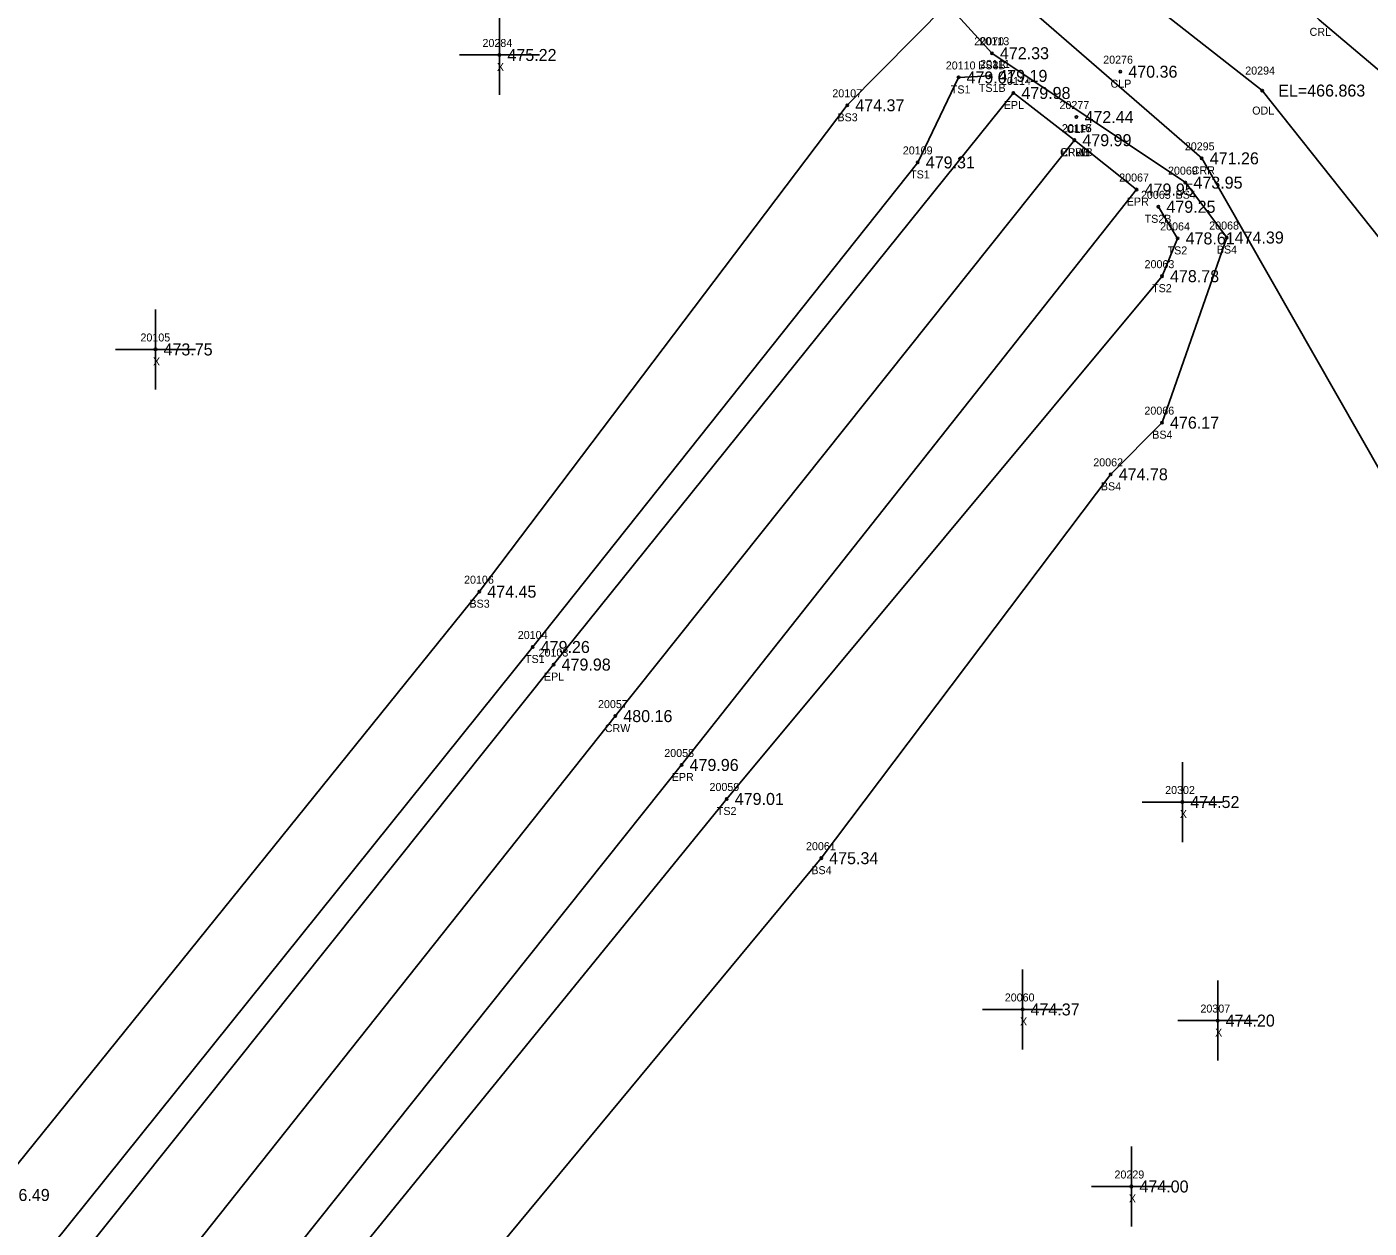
# Model space of a CAD drawing. Extents: x 1789565 to 1790548, y 909019 to 910194.
# Drawn here: x 1789914 to 1790081.8, y 909456.7 to 909606.8 of the extents above; entities that cross this region are included whole.
import ezdxf

# ---------------------------------------------------------------- set-up
doc = ezdxf.new("R2010")
doc.units = 0
for name, color, linetype in [('RD_DTM_BkLn1', 7, 'Continuous'), ('RD_DTM_BkLn2', 7, 'Continuous'), ('RD_DTM_BkLn_txCode', 7, 'Continuous'), ('RD_EX_H2O', 7, 'Continuous'), ('RD_EX_H2O_txCode', 7, 'Continuous'), ('RD_EX_Misc', 7, 'Continuous'), ('RD_EX_Misc_txCode', 7, 'Continuous'), ('RD_EX_Road', 7, 'Continuous'), ('RD_EX_Road_txCode', 7, 'Continuous'), ('RD_EX_TX_H2O_ELEV', 7, 'Continuous'), ('RD_EX_TX_Misc_ELEV', 7, 'Continuous'), ('RD_EX_TX_Road_ELEV', 7, 'Continuous'), ('RD_HC_Survey_ELEV', 7, 'Continuous'), ('RD_HC_Survey_txCode', 7, 'Continuous'), ('RD_SMD_Locator', 7, 'Continuous')]:
    doc.layers.add(name, color=color, linetype=linetype)

msp = doc.modelspace()

# ---------------------------------------------------------------- linework, layer by layer
at = {"layer": 'RD_DTM_BkLn1'}
msp.add_lwpolyline([(1789624.5, 909066.24), (1789686.15, 909143.09), (1789745.11, 909217.37), (1789803.6, 909290.4), (1789864.63, 909366.97), (1789927.82, 909445.41), (1789987.57, 909520.69), (1790044.94, 909592.68)], dxfattribs=at)
at = {"layer": 'RD_DTM_BkLn2'}
for points in [[(1789838.38, 909362.25), (1789846.95, 909377.91), (1789909.75, 909460.83), (1789970.57, 909536.24), (1790016.56, 909597.04), (1790029.06, 909609.68), (1790034.63, 909603.55)], [(1789902.5, 909352.17), (1789901.93, 909363.56), (1789951.8, 909428.72), (1790013.3, 909502.93), (1790049.48, 909550.91), (1790055.89, 909557.37), (1790063.97, 909580.51), (1790058.82, 909587.37), (1790034.63, 909603.55)], [(1789614.08, 909073.14), (1789676.68, 909150.35), (1789735.2, 909226.02), (1789793.81, 909297.32), (1789853.39, 909374.42), (1789917.15, 909454.46), (1789977.25, 909529.33), (1790025.37, 909589.9), (1790030.46, 909600.52), (1790034.43, 909600.71)], [(1789900.24, 909342.75), (1789881.76, 909350.91), (1789880.04, 909360.95), (1789940.57, 909435.39), (1790001.5, 909510.33), (1790055.89, 909575.68), (1790057.84, 909580.4), (1790055.44, 909584.35)]]:
    msp.add_lwpolyline(points, dxfattribs=at)
at = {"layer": 'RD_EX_H2O'}
for points in [[(1789926.75, 910151.78), (1789921.87, 910061.22), (1789923.33, 910015.8), (1789922.65, 909953.15), (1789957.79, 909859.65), (1789976.3, 909811.78), (1790009.05, 909737.59), (1790033.3, 909656.58), (1790043.84, 909640.77), (1790040.94, 909620.44), (1790068.41, 909598.88), (1790105.46, 909552.21), (1790128.28, 909493.4), (1790125.72, 909445.59), (1790167.31, 909436.17), (1790202.14, 909447.88), (1790216.41, 909437.36), (1790196.97, 909382.86), (1790209.47, 909371.8), (1790248.65, 909379.51), (1790333.47, 909404.65), (1790412.72, 909370.84), (1790438.82, 909377.48), (1790480.23, 909327.32)], [(1789942.19, 910149.47), (1789928.94, 910061.47), (1789937.03, 910016.56), (1789929.09, 909954.8), (1789962.46, 909861.74), (1789984.97, 909814.65), (1790017.82, 909740.15), (1790045.4, 909660.05), (1790055.69, 909646.96), (1790055.38, 909644.82), (1790053.69, 909634.91), (1790054.91, 909627.64), (1790075.55, 909607.72), (1790122.18, 909568.31), (1790142.55, 909490.86), (1790145.56, 909467.27), (1790204.21, 909464.64), (1790228.21, 909444.34), (1790208.83, 909385.44), (1790245.53, 909398.45), (1790340.56, 909420.98), (1790422.56, 909390.06), (1790444.95, 909390.88), (1790496, 909329.5)], [(1790030.97, 909616.21), (1790039.23, 909609.17), (1790060.86, 909590.41), (1790089.09, 909540.87), (1790093.77, 909497), (1790113.81, 909430.51), (1790177.09, 909424.59), (1790197.54, 909430.06), (1790185.17, 909386.39), (1790196.62, 909365.47), (1790247.61, 909363.63), (1790324.38, 909372.65), (1790407.18, 909352.01), (1790424.72, 909347.04), (1790471.09, 909309.36)]]:
    msp.add_lwpolyline(points, dxfattribs=at)
at = {"layer": 'RD_EX_Misc'}
for p, q in [((1789973.09, 909598.33), (1789973.09, 909608.33)), ((1789968.09, 909603.33), (1789978.09, 909603.33)), ((1789930.11, 909561.52), (1789930.11, 909571.52)), ((1789925.11, 909566.52), (1789935.11, 909566.52)), ((1790058.43, 909504.95), (1790058.43, 909514.95)), ((1790053.43, 909509.95), (1790063.43, 909509.95)), ((1790038.46, 909479.02), (1790038.46, 909489.02)), ((1790062.85, 909477.63), (1790062.85, 909487.63)), ((1790033.46, 909484.02), (1790043.46, 909484.02)), ((1790057.85, 909482.63), (1790067.85, 909482.63)), ((1790052.07, 909456.89), (1790052.07, 909466.89)), ((1790047.07, 909461.89), (1790057.07, 909461.89))]:
    msp.add_line(p, q, dxfattribs=at)
at = {"layer": 'RD_EX_Road'}
for points in [[(1789616.04, 909073.03), (1789678, 909149.36), (1789737.65, 909223.89), (1789795.32, 909296.33), (1789856.01, 909372.29), (1789919.82, 909451.94), (1789979.86, 909527.13), (1790037.32, 909598.58), (1790044.94, 909592.68)], [(1789632.25, 909060.17), (1789693.63, 909136.51), (1789752.94, 909210.84), (1789811.79, 909284.47), (1789846.6, 909328.43), (1789872.88, 909361.39), (1789936.05, 909439.58), (1789995.85, 909514.58), (1790052.72, 909586.51), (1790044.94, 909592.68)]]:
    msp.add_lwpolyline(points, dxfattribs=at)
at = {"layer": 'RD_SMD_Locator'}
for centre in [(1789973.09, 909603.33), (1790034.63, 909603.55), (1790034.63, 909603.55), (1790030.46, 909600.52), (1790034.43, 909600.71), (1790050.68, 909601.24), (1790037.32, 909598.58), (1790068.41, 909598.88), (1790016.56, 909597.04), (1790045.2, 909595.57), (1790044.94, 909592.68), (1790044.94, 909592.68), (1790044.94, 909592.68), (1790060.86, 909590.41), (1790025.37, 909589.9), (1790058.82, 909587.37), (1790052.72, 909586.51), (1790055.44, 909584.35), (1790057.84, 909580.4), (1790063.97, 909580.51), (1790055.89, 909575.68), (1789930.11, 909566.52), (1790055.89, 909557.37), (1790049.48, 909550.91), (1789970.57, 909536.24), (1789977.25, 909529.33), (1789979.86, 909527.13), (1789987.57, 909520.69), (1789995.85, 909514.58), (1790001.5, 909510.33), (1790058.43, 909509.95), (1790013.3, 909502.93), (1790038.46, 909484.02), (1790062.85, 909482.63), (1790052.07, 909461.89)]:
    msp.add_circle(centre, 0.15, dxfattribs=at)

# ---------------------------------------------------------------- texts
at = {"layer": 'RD_DTM_BkLn_txCode'}
for s, p in [('20070', (1790032.43, 909604.55)), ('20113', (1790033.08, 909604.55)), ('20110', (1790028.87, 909601.52)), ('BS4B', (1790032.93, 909601.55)), ('BS3B', (1790032.93, 909601.55)), ('20111', (1790033.16, 909601.71)), ('20107', (1790014.69, 909598.04)), ('TS1', (1790029.5, 909598.52)), ('TS1B', (1790033, 909598.71)), ('BS3', (1790015.33, 909595.04)), ('20109', (1790023.5, 909590.9)), ('TS1', (1790024.41, 909587.9)), ('20069', (1790056.64, 909588.37)), ('20065', (1790053.26, 909585.35)), ('BS4', (1790057.59, 909585.37)), ('TS2B', (1790053.72, 909582.35)), ('20064', (1790055.66, 909581.4)), ('20068', (1790061.79, 909581.51)), ('TS2', (1790056.59, 909578.4)), ('BS4', (1790062.74, 909578.51)), ('20063', (1790053.71, 909576.68)), ('TS2', (1790054.65, 909573.68)), ('20066', (1790053.69, 909558.37)), ('BS4', (1790054.67, 909555.37)), ('20062', (1790047.3, 909551.91)), ('BS4', (1790048.25, 909548.91)), ('20106', (1789968.67, 909537.24)), ('BS3', (1789969.34, 909534.24)), ('20104', (1789975.38, 909530.33)), ('TS1', (1789976.29, 909527.33)), ('20059', (1789999.34, 909511.33)), ('TS2', (1790000.26, 909508.33)), ('20061', (1790011.4, 909503.93)), ('BS4', (1790012.07, 909500.93))]:
    msp.add_text(s, height=1, dxfattribs=at).set_placement(p)
at = {"layer": 'RD_EX_H2O_txCode'}
for s, p in [('CRL', (1790074.33, 909605.72)), ('20294', (1790066.29, 909600.88)), ('ODL', (1790067.16, 909595.88)), ('20295', (1790058.74, 909591.41)), ('CRR', (1790059.61, 909588.41))]:
    msp.add_text(s, height=1, dxfattribs=at).set_placement(p)
at = {"layer": 'RD_EX_Misc_txCode'}
for s, p in [('20284', (1789970.97, 909604.33)), ('X', (1789972.77, 909601.33)), ('20105', (1789928.23, 909567.52)), ('X', (1789929.79, 909564.52)), ('20302', (1790056.28, 909510.95)), ('X', (1790058.12, 909507.95)), ('20060', (1790036.24, 909485.02)), ('20307', (1790060.69, 909483.63)), ('X', (1790038.15, 909482.02)), ('X', (1790062.53, 909480.63)), ('20229', (1790049.95, 909462.89)), ('X', (1790051.75, 909459.89))]:
    msp.add_text(s, height=1, dxfattribs=at).set_placement(p)
at = {"layer": 'RD_EX_Road_txCode'}
for s, p in [('20114', (1790035.77, 909599.58)), ('EPL', (1790036.11, 909596.58)), ('20116', (1790043.36, 909593.68)), ('20115', (1790043.39, 909593.68)), ('EPRB', (1790043.24, 909590.68)), ('EPLB', (1790043.26, 909590.68)), ('20067', (1790050.54, 909587.51)), ('EPR', (1790051.49, 909584.51)), ('20103', (1789977.98, 909528.13)), ('EPL', (1789978.65, 909525.13)), ('20058', (1789993.69, 909515.58)), ('EPR', (1789994.62, 909512.58))]:
    msp.add_text(s, height=1, dxfattribs=at).set_placement(p)
at = {"layer": 'RD_EX_TX_H2O_ELEV'}
for s, p in [('EL=466.863', (1790070.41, 909598.13)), ('471.26', (1790061.86, 909589.66))]:
    msp.add_text(s, height=1.5, dxfattribs=at).set_placement(p)
at = {"layer": 'RD_EX_TX_Misc_ELEV'}
for s, p in [('475.22', (1789974.09, 909602.58)), ('472.33', (1790035.63, 909602.8)), ('472.33', (1790035.63, 909602.8)), ('479.01', (1790031.46, 909599.77)), ('479.19', (1790035.43, 909599.96)), ('474.37', (1790017.56, 909596.29)), ('479.31', (1790026.37, 909589.15)), ('473.95', (1790059.82, 909586.62)), ('479.25', (1790056.44, 909583.6)), ('478.61', (1790058.84, 909579.65)), ('474.39', (1790064.97, 909579.76)), ('478.78', (1790056.89, 909574.93)), ('473.75', (1789931.11, 909565.77)), ('476.17', (1790056.89, 909556.62)), ('474.78', (1790050.48, 909550.16)), ('474.45', (1789971.57, 909535.49)), ('479.26', (1789978.25, 909528.58)), ('479.01', (1790002.5, 909509.58)), ('474.52', (1790059.43, 909509.2)), ('475.34', (1790014.3, 909502.18)), ('474.37', (1790039.46, 909483.27)), ('474.20', (1790063.85, 909481.88)), ('476.49', (1789910.75, 909460.08)), ('474.00', (1790053.07, 909461.14))]:
    msp.add_text(s, height=1.5, dxfattribs=at).set_placement(p)
at = {"layer": 'RD_EX_TX_Road_ELEV'}
for s, p in [('479.98', (1790038.32, 909597.83)), ('479.99', (1790045.94, 909591.93)), ('479.99', (1790045.94, 909591.93)), ('479.95', (1790053.72, 909585.76)), ('479.98', (1789980.86, 909526.38)), ('479.96', (1789996.85, 909513.83))]:
    msp.add_text(s, height=1.5, dxfattribs=at).set_placement(p)
at = {"layer": 'RD_HC_Survey_ELEV'}
for s, p in [('470.36', (1790051.68, 909600.49)), ('472.44', (1790046.2, 909594.82)), ('479.99', (1790045.94, 909591.93)), ('480.16', (1789988.57, 909519.94))]:
    msp.add_text(s, height=1.5, dxfattribs=at).set_placement(p)
at = {"layer": 'RD_HC_Survey_txCode'}
for s, p in [('20276', (1790048.54, 909602.24)), ('CLP', (1790049.46, 909599.24)), ('20277', (1790043.08, 909596.57)), ('20117', (1790043.39, 909593.68)), ('CLP', (1790043.97, 909593.57)), ('CRWB', (1790043.15, 909590.68)), ('20057', (1789985.41, 909521.69)), ('CRW', (1789986.26, 909518.69))]:
    msp.add_text(s, height=1, dxfattribs=at).set_placement(p)

doc.saveas('drawing.dxf')
